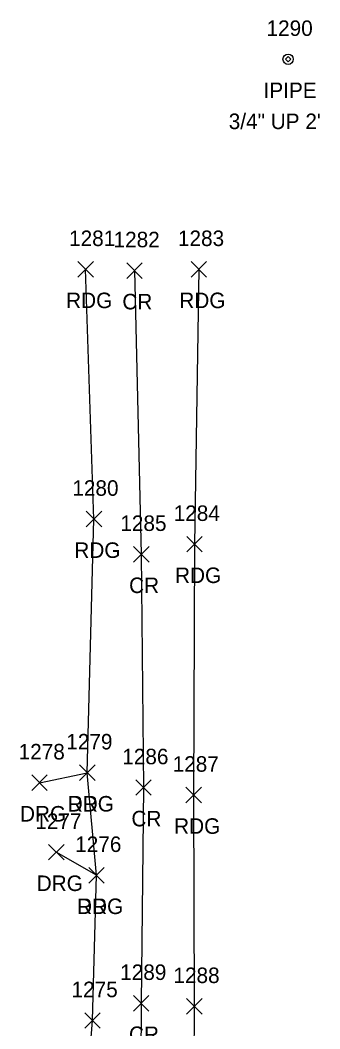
# Model space of a CAD drawing. Extents: x 1657482 to 1661439, y 647981 to 649041.
# Drawn here: x 1659792.5 to 1659831.1, y 648225 to 648354.9 of the extents above; entities that cross this region are included whole.
import ezdxf

# ---------------------------------------------------------------- set-up
doc = ezdxf.new("R2010")
doc.units = 0
for name, color, linetype in [('M_A', 7, 'Continuous'), ('M_C', 7, 'Continuous'), ('M_I', 7, 'Continuous'), ('MPIP', 7, 'Continuous'), ('P_A', 7, 'Continuous'), ('P_I', 7, 'Continuous'), ('P_TIC', 7, 'Continuous'), ('PEU', 7, 'Continuous'), ('PRC', 7, 'Continuous'), ('R_A', 7, 'Continuous'), ('R_I', 7, 'Continuous'), ('R_TIC', 7, 'Continuous'), ('RDG', 7, 'Continuous')]:
    doc.layers.add(name, color=color, linetype=linetype)

msp = doc.modelspace()

# ---------------------------------------------------------------- linework, layer by layer
at = {"layer": 'MPIP'}
msp.add_lwpolyline([(1659827.34, 648349.89), (1659827, 648350.23), (1659826.67, 648349.89), (1659827, 648349.56)], close=True, dxfattribs=at)
msp.add_circle((1659827, 648349.89), 0.667, dxfattribs=at)
at = {"layer": 'P_TIC'}
for points in [[(1659799.92, 648321.82), (1659801.92, 648323.82)], [(1659801.92, 648321.82), (1659799.92, 648323.82)], [(1659806.22, 648321.66), (1659808.22, 648323.66)], [(1659808.22, 648321.66), (1659806.22, 648323.66)], [(1659814.51, 648321.82), (1659816.51, 648323.82)], [(1659816.51, 648321.82), (1659814.51, 648323.82)], [(1659800.99, 648289.64), (1659802.99, 648291.64)], [(1659802.99, 648289.64), (1659800.99, 648291.64)], [(1659813.95, 648286.4), (1659815.95, 648288.4)], [(1659815.95, 648286.4), (1659813.95, 648288.4)], [(1659807.09, 648285.11), (1659809.09, 648287.11)], [(1659809.09, 648285.11), (1659807.09, 648287.11)], [(1659800.13, 648256.96), (1659802.13, 648258.96)], [(1659802.13, 648256.96), (1659800.13, 648258.96)], [(1659807.38, 648255.05), (1659809.38, 648257.05)], [(1659809.38, 648255.05), (1659807.38, 648257.05)], [(1659813.83, 648254.09), (1659815.83, 648256.09)], [(1659815.83, 648254.09), (1659813.83, 648256.09)], [(1659801.33, 648243.75), (1659803.33, 648245.75)], [(1659803.33, 648243.75), (1659801.33, 648245.75)], [(1659807.07, 648227.26), (1659809.07, 648229.26)], [(1659809.07, 648227.26), (1659807.07, 648229.26)], [(1659813.92, 648226.86), (1659815.92, 648228.86)], [(1659815.92, 648226.86), (1659813.92, 648228.86)], [(1659800.8, 648225.04), (1659802.8, 648227.04)], [(1659802.8, 648225.04), (1659800.8, 648227.04)]]:
    msp.add_lwpolyline(points, dxfattribs=at)
at = {"layer": 'PEU'}
for points in [[(1659797.28, 648121.74), (1659797.87, 648123.93), (1659798.34, 648135.51), (1659799.28, 648146.42), (1659800, 648161.86), (1659799.83, 648177.81), (1659798.75, 648186.93), (1659801.8, 648226.04), (1659802.33, 648244.75), (1659801.13, 648257.96), (1659801.99, 648290.64), (1659800.92, 648322.82)], [(1659815.51, 648322.82), (1659814.95, 648287.4), (1659814.83, 648255.09), (1659814.92, 648227.86), (1659814.78, 648205.42), (1659814.27, 648180.51), (1659814.09, 648160.02), (1659817.14, 648140.38), (1659817.84, 648129.18), (1659822.06, 648119.73)]]:
    msp.add_lwpolyline(points, dxfattribs=at)
at = {"layer": 'PRC'}
msp.add_lwpolyline([(1659807.22, 648322.66), (1659808.09, 648286.11), (1659808.38, 648256.05), (1659808.07, 648228.26), (1659807.95, 648205.15), (1659807.09, 648180.37), (1659807.15, 648158.51), (1659808.36, 648139.11), (1659809.07, 648120.36)], dxfattribs=at)
at = {"layer": 'R_TIC'}
for points in [[(1659800.13, 648256.96), (1659802.13, 648258.96)], [(1659802.13, 648256.96), (1659800.13, 648258.96)], [(1659793.98, 648255.67), (1659795.98, 648257.67)], [(1659795.98, 648255.67), (1659793.98, 648257.67)], [(1659796.14, 648246.72), (1659798.14, 648248.72)], [(1659798.14, 648246.72), (1659796.14, 648248.72)], [(1659801.33, 648243.75), (1659803.33, 648245.75)], [(1659803.33, 648243.75), (1659801.33, 648245.75)]]:
    msp.add_lwpolyline(points, dxfattribs=at)
at = {"layer": 'RDG'}
for points in [[(1659794.98, 648256.67), (1659801.13, 648257.96)], [(1659802.33, 648244.75), (1659797.14, 648247.72)]]:
    msp.add_lwpolyline(points, dxfattribs=at)

# ---------------------------------------------------------------- texts
at = {"layer": 'M_A'}
msp.add_text('IPIPE', height=2, dxfattribs=at).set_placement((1659823.84, 648344.89))
at = {"layer": 'M_C'}
msp.add_text('3/4" UP 2\'', height=2, dxfattribs=at).set_placement((1659819.35, 648340.89))
at = {"layer": 'M_I'}
msp.add_text('1290', height=2, dxfattribs=at).set_placement((1659824.22, 648352.89))
at = {"layer": 'P_A'}
for s, p in [('RDG', (1659798.41, 648317.82)), ('CR', (1659805.65, 648317.66)), ('RDG', (1659812.99, 648317.82)), ('RDG', (1659799.47, 648285.64)), ('RDG', (1659812.44, 648282.4)), ('CR', (1659806.52, 648281.11)), ('RDG', (1659798.62, 648252.96)), ('CR', (1659806.82, 648251.05)), ('RDG', (1659812.32, 648250.09)), ('RDG', (1659799.82, 648239.75)), ('CR', (1659806.51, 648223.26))]:
    msp.add_text(s, height=2, dxfattribs=at).set_placement(p)
at = {"layer": 'P_I'}
for s, p in [('1281', (1659798.79, 648325.82)), ('1282', (1659804.52, 648325.66)), ('1283', (1659812.81, 648325.82)), ('1280', (1659799.21, 648293.64)), ('1284', (1659812.26, 648290.4)), ('1285', (1659805.39, 648289.11)), ('1279', (1659798.43, 648260.96)), ('1286', (1659805.64, 648259.05)), ('1287', (1659812.13, 648258.09)), ('1276', (1659799.58, 648247.75)), ('1289', (1659805.37, 648231.26)), ('1288', (1659812.23, 648230.86)), ('1275', (1659799.11, 648229.04))]:
    msp.add_text(s, height=2, dxfattribs=at).set_placement(p)
at = {"layer": 'R_A'}
for p in [(1659798.62, 648252.96), (1659792.47, 648251.67), (1659794.62, 648242.72), (1659799.82, 648239.75)]:
    msp.add_text('DRG', height=2, dxfattribs=at).set_placement(p)
at = {"layer": 'R_I'}
for s, p in [('1279', (1659798.43, 648260.96)), ('1278', (1659792.29, 648259.67)), ('1277', (1659794.44, 648250.72)), ('1276', (1659799.58, 648247.75))]:
    msp.add_text(s, height=2, dxfattribs=at).set_placement(p)

doc.saveas('drawing.dxf')
